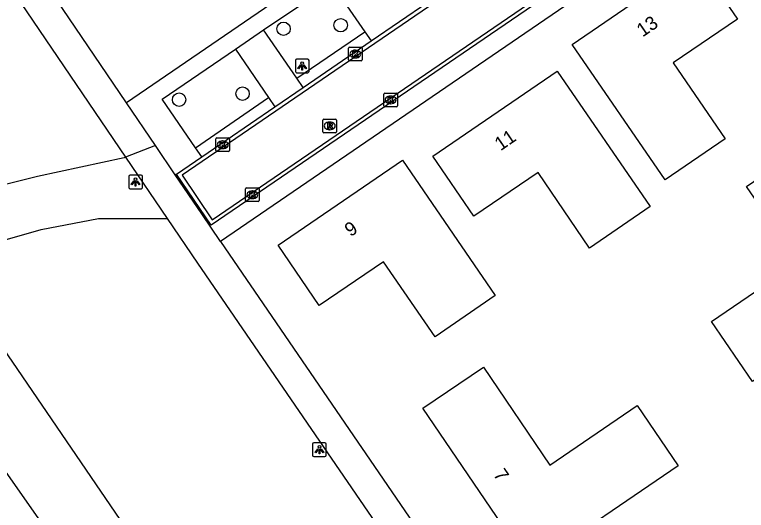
# Model space of a CAD drawing. Extents: x 155275 to 156263, y 382654 to 383635.
# Drawn here: x 155466.7 to 155520.2, y 383140.8 to 383177 of the extents above; entities that cross this region are included whole.
import ezdxf

# ---------------------------------------------------------------- set-up
doc = ezdxf.new("R2010")
doc.units = 0
for name, color, linetype in [('IMGEO_Boom', 7, 'Continuous'), ('IMGEO_Groenvoorziening', 7, 'Continuous'), ('IMGEO_Kolk', 7, 'Continuous'), ('IMGEO_Lichtpunt', 7, 'Continuous'), ('IMGEO_Pand', 7, 'Continuous'), ('IMGEO_Pand_nummerreeks', 7, 'Continuous'), ('IMGEO_Parkeervlak_open', 7, 'Continuous'), ('IMGEO_Rijbaan_lokaal_gesloten', 7, 'Continuous'), ('IMGEO_Rioolput', 7, 'Continuous'), ('IMGEO_Voetpad_halfverhard', 7, 'Continuous'), ('IMGEO_Voetpad_open', 7, 'Continuous')]:
    doc.layers.add(name, color=color, linetype=linetype)

msp = doc.modelspace()

# ---------------------------------------------------------------- linework, layer by layer
at = {"layer": 'IMGEO_Boom'}
for centre in [(155490.508, 383176.25), (155486.336, 383175.992), (155478.702, 383170.812), (155483.34, 383171.251)]:
    msp.add_circle(centre, 0.489, dxfattribs=at)
at = {"layer": 'IMGEO_Groenvoorziening'}
msp.add_lwpolyline([(155532.26, 383055.303), (155462.233, 383157.915)], dxfattribs=at)
at = {"layer": 'IMGEO_Kolk'}
for p, q in [((155491.078, 383173.722), (155491.078, 383174.574)), ((155491.153, 383174.648), (155492.005, 383174.648)), ((155492.079, 383174.574), (155492.079, 383173.722)), ((155491.566, 383174.428), (155491.591, 383174.428)), ((155492.005, 383173.648), (155491.153, 383173.648)), ((155491.589, 383173.868), (155491.564, 383173.868)), ((155493.729, 383171.297), (155494.581, 383171.297)), ((155493.654, 383170.371), (155493.654, 383171.223)), ((155494.142, 383171.077), (155494.167, 383171.077)), ((155494.655, 383171.223), (155494.655, 383170.371)), ((155494.581, 383170.297), (155493.729, 383170.297)), ((155494.165, 383170.517), (155494.14, 383170.517)), ((155481.39, 383167.092), (155481.39, 383167.944)), ((155481.465, 383168.018), (155482.317, 383168.018)), ((155481.878, 383167.798), (155481.903, 383167.798)), ((155482.391, 383167.944), (155482.391, 383167.092)), ((155482.317, 383167.018), (155481.465, 383167.018)), ((155481.901, 383167.238), (155481.876, 383167.238)), ((155483.626, 383164.367), (155484.478, 383164.367)), ((155483.551, 383163.441), (155483.551, 383164.293)), ((155484.039, 383164.147), (155484.064, 383164.147)), ((155484.552, 383164.293), (155484.552, 383163.441)), ((155484.478, 383163.367), (155483.626, 383163.367)), ((155484.062, 383163.587), (155484.037, 383163.587))]:
    msp.add_line(p, q, dxfattribs=at)
for points in [[(155491.078, 383173.722), (155491.078, 383174.574)], [(155491.153, 383174.648), (155492.005, 383174.648)], [(155492.079, 383174.574), (155492.079, 383173.722)], [(155491.399, 383174.348), (155491.522, 383174.348), (155491.522, 383174.197), (155491.652, 383174.348), (155491.816, 383174.348), (155491.67, 383174.197), (155491.823, 383173.948), (155491.671, 383173.948), (155491.586, 383174.112), (155491.522, 383174.045), (155491.522, 383173.948), (155491.399, 383173.948), (155491.399, 383174.348)], [(155492.005, 383173.648), (155491.153, 383173.648)], [(155493.729, 383171.297), (155494.581, 383171.297)], [(155493.654, 383170.371), (155493.654, 383171.223)], [(155493.975, 383170.997), (155494.098, 383170.997), (155494.098, 383170.846), (155494.228, 383170.997), (155494.392, 383170.997), (155494.246, 383170.846), (155494.399, 383170.597), (155494.247, 383170.597), (155494.162, 383170.761), (155494.098, 383170.694), (155494.098, 383170.597), (155493.975, 383170.597), (155493.975, 383170.997)], [(155494.655, 383171.223), (155494.655, 383170.371)], [(155494.581, 383170.297), (155493.729, 383170.297)], [(155481.39, 383167.092), (155481.39, 383167.944)], [(155481.465, 383168.018), (155482.317, 383168.018)], [(155481.711, 383167.718), (155481.834, 383167.718), (155481.834, 383167.567), (155481.964, 383167.718), (155482.128, 383167.718), (155481.982, 383167.567), (155482.135, 383167.318), (155481.983, 383167.318), (155481.898, 383167.482), (155481.834, 383167.415), (155481.834, 383167.318), (155481.711, 383167.318), (155481.711, 383167.718)], [(155482.391, 383167.944), (155482.391, 383167.092)], [(155482.317, 383167.018), (155481.465, 383167.018)], [(155483.626, 383164.367), (155484.478, 383164.367)], [(155483.551, 383163.441), (155483.551, 383164.293)], [(155483.872, 383164.067), (155483.995, 383164.067), (155483.995, 383163.916), (155484.125, 383164.067), (155484.289, 383164.067), (155484.143, 383163.916), (155484.296, 383163.667), (155484.144, 383163.667), (155484.059, 383163.831), (155483.995, 383163.764), (155483.995, 383163.667), (155483.872, 383163.667), (155483.872, 383164.067)], [(155484.552, 383164.293), (155484.552, 383163.441)], [(155484.478, 383163.367), (155483.626, 383163.367)]]:
    msp.add_lwpolyline(points, dxfattribs=at)
for centre, start, end in [((155491.155, 383174.572), 91.552, 178.448), ((155491.155, 383174.572), 91.552, 178.448), ((155492.003, 383174.572), 1.552, 88.448), ((155492.003, 383174.572), 1.552, 88.448), ((155491.155, 383173.724), 181.552, 268.448), ((155491.155, 383173.724), 181.552, 268.448), ((155492.003, 383173.724), 271.552, 358.448), ((155492.003, 383173.724), 271.552, 358.448), ((155493.731, 383171.221), 91.552, 178.448), ((155493.731, 383171.221), 91.552, 178.448), ((155494.579, 383171.221), 1.552, 88.448), ((155494.579, 383171.221), 1.552, 88.448), ((155493.731, 383170.373), 181.552, 268.448), ((155493.731, 383170.373), 181.552, 268.448), ((155494.579, 383170.373), 271.552, 358.448), ((155494.579, 383170.373), 271.552, 358.448), ((155481.467, 383167.942), 91.552, 178.448), ((155481.467, 383167.942), 91.552, 178.448), ((155482.315, 383167.942), 1.552, 88.448), ((155482.315, 383167.942), 1.552, 88.448), ((155481.467, 383167.094), 181.552, 268.448), ((155481.467, 383167.094), 181.552, 268.448), ((155482.315, 383167.094), 271.552, 358.448), ((155482.315, 383167.094), 271.552, 358.448), ((155483.628, 383164.291), 91.552, 178.448), ((155483.628, 383164.291), 91.552, 178.448), ((155484.476, 383164.291), 1.552, 88.448), ((155484.476, 383164.291), 1.552, 88.448), ((155483.628, 383163.443), 181.552, 268.448), ((155483.628, 383163.443), 181.552, 268.448), ((155484.476, 383163.443), 271.552, 358.448), ((155484.476, 383163.443), 271.552, 358.448)]:
    msp.add_arc(centre, 0.0765, start, end, dxfattribs=at)
for centre, major_axis, ratio, start_param, end_param in [((155491.565, 383174.148), (-0.387, 0.002), 0.722429, 4.712389, 7.853982), ((155491.59, 383174.148), (-0.39, 0.002), 0.717154, 1.570796, 4.712389), ((155494.141, 383170.797), (-0.387, 0.002), 0.722429, 4.712389, 7.853982), ((155494.166, 383170.797), (-0.39, 0.002), 0.717154, 1.570796, 4.712389), ((155481.877, 383167.518), (-0.387, 0.002), 0.722429, 4.712389, 7.853982), ((155481.902, 383167.518), (-0.39, 0.002), 0.717154, 1.570796, 4.712389), ((155484.038, 383163.867), (-0.387, 0.002), 0.722429, 4.712389, 7.853982), ((155484.063, 383163.867), (-0.39, 0.002), 0.717154, 1.570796, 4.712389)]:
    msp.add_ellipse(centre, major_axis=major_axis, ratio=ratio, start_param=start_param, end_param=end_param, dxfattribs=at)
at = {"layer": 'IMGEO_Lichtpunt'}
for p, q in [((155487.198, 383173.685), (155487.198, 383172.878)), ((155487.198, 383173.685), (155487.198, 383172.878)), ((155488.1, 383173.78), (155487.292, 383173.78)), ((155488.1, 383173.78), (155487.292, 383173.78)), ((155488.194, 383172.878), (155488.194, 383173.685)), ((155488.194, 383172.878), (155488.194, 383173.685)), ((155487.292, 383172.784), (155488.1, 383172.784)), ((155487.292, 383172.784), (155488.1, 383172.784)), ((155475.023, 383165.21), (155475.023, 383164.403)), ((155475.023, 383165.21), (155475.023, 383164.403)), ((155475.925, 383165.305), (155475.117, 383165.305)), ((155475.925, 383165.305), (155475.117, 383165.305)), ((155476.019, 383164.403), (155476.019, 383165.21)), ((155476.019, 383164.403), (155476.019, 383165.21)), ((155475.117, 383164.309), (155475.925, 383164.309)), ((155475.117, 383164.309), (155475.925, 383164.309)), ((155488.456, 383145.64), (155488.456, 383144.833)), ((155488.456, 383145.64), (155488.456, 383144.833)), ((155489.358, 383145.735), (155488.55, 383145.735)), ((155489.358, 383145.735), (155488.55, 383145.735)), ((155489.452, 383144.833), (155489.452, 383145.64)), ((155489.452, 383144.833), (155489.452, 383145.64)), ((155488.55, 383144.739), (155489.358, 383144.739)), ((155488.55, 383144.739), (155489.358, 383144.739))]:
    msp.add_line(p, q, dxfattribs=at)
for points in [[(155487.572, 383173.349), (155487.611, 383173.321), (155487.423, 383173.059), (155487.385, 383173.086), (155487.572, 383173.349)], [(155487.674, 383173.301), (155487.721, 383173.301), (155487.721, 383172.979), (155487.674, 383172.979), (155487.674, 383173.301)], [(155487.784, 383173.321), (155487.822, 383173.348), (155488.009, 383173.086), (155487.97, 383173.058), (155487.784, 383173.321)], [(155475.397, 383164.874), (155475.436, 383164.846), (155475.248, 383164.584), (155475.21, 383164.611), (155475.397, 383164.874)], [(155475.609, 383164.846), (155475.647, 383164.873), (155475.834, 383164.611), (155475.795, 383164.583), (155475.609, 383164.846)], [(155475.499, 383164.826), (155475.546, 383164.826), (155475.546, 383164.504), (155475.499, 383164.504), (155475.499, 383164.826)], [(155488.83, 383145.304), (155488.869, 383145.276), (155488.681, 383145.014), (155488.643, 383145.041), (155488.83, 383145.304)], [(155488.932, 383145.256), (155488.979, 383145.256), (155488.979, 383144.934), (155488.932, 383144.934), (155488.932, 383145.256)], [(155489.042, 383145.276), (155489.08, 383145.303), (155489.267, 383145.041), (155489.228, 383145.013), (155489.042, 383145.276)]]:
    msp.add_lwpolyline(points, dxfattribs=at)
for centre in [(155487.697, 383173.483), (155475.522, 383165.008), (155488.955, 383145.438)]:
    msp.add_circle(centre, 0.0994, dxfattribs=at)
for centre, start, end in [((155487.292, 383173.685), 90, 180), ((155487.292, 383173.685), 90, 180), ((155488.1, 383173.685), 0, 90), ((155488.1, 383173.685), 0, 90), ((155487.292, 383172.878), 180, 270), ((155487.292, 383172.878), 180, 270), ((155488.1, 383172.878), 270, 0), ((155488.1, 383172.878), 270, 360), ((155475.117, 383165.21), 90, 180), ((155475.117, 383165.21), 90, 180), ((155475.925, 383165.21), 0, 90), ((155475.925, 383165.21), 0, 90), ((155475.117, 383164.403), 180, 270), ((155475.117, 383164.403), 180, 270), ((155475.925, 383164.403), 270, 0), ((155475.925, 383164.403), 270, 360), ((155488.55, 383145.64), 90, 180), ((155488.55, 383145.64), 90, 180), ((155489.358, 383145.64), 0, 90), ((155489.358, 383145.64), 0, 90), ((155488.55, 383144.833), 180, 270), ((155488.55, 383144.833), 180, 270), ((155489.358, 383144.833), 270, 0), ((155489.358, 383144.833), 270, 360)]:
    msp.add_arc(centre, 0.0946, start, end, dxfattribs=at)
at = {"layer": 'IMGEO_Pand'}
for points in [[(155518.605, 383167.962), (155514.21, 383164.968), (155507.415, 383174.849), (155516.52, 383181.09), (155519.515, 383176.693), (155514.811, 383173.493), (155518.605, 383167.962)], [(155513.126, 383163.01), (155508.698, 383159.972), (155504.944, 383165.502), (155500.249, 383162.295), (155497.248, 383166.689), (155506.329, 383172.897), (155513.126, 383163.01)], [(155531.374, 383157.564), (155520.608, 383150.215), (155517.615, 383154.608), (155523.957, 383158.929), (155520.168, 383164.469), (155524.592, 383167.478), (155531.374, 383157.564)], [(155501.806, 383156.503), (155497.424, 383153.478), (155493.637, 383158.963), (155488.93, 383155.776), (155485.946, 383160.182), (155495.036, 383166.388), (155501.806, 383156.503)], [(155500.946, 383151.275), (155505.801, 383144.112), (155512.165, 383148.464), (155515.17, 383144.069), (155504.385, 383136.699), (155496.513, 383148.271), (155500.946, 383151.275)]]:
    msp.add_lwpolyline(points, dxfattribs=at)
at = {"layer": 'IMGEO_Parkeervlak_open'}
for points in [[(155489.868, 383179.279), (155492.272, 383175.772)], [(155487.309, 383172.386), (155484.874, 383175.918)], [(155482.819, 383174.511), (155485.236, 383170.964)]]:
    msp.add_lwpolyline(points, dxfattribs=at)
at = {"layer": 'IMGEO_Rijbaan_lokaal_gesloten'}
for points in [[(155619.924, 383262.117), (155620.091, 383261.877), (155574.69, 383230.764), (155525.625, 383197.223), (155478.919, 383165.304), (155481.12, 383162.042), (155527.802, 383193.934), (155576.261, 383227.078), (155622.367, 383258.594), (155622.544, 383258.352)], [(155517.341, 383186.428), (155481.036, 383161.64), (155478.515, 383165.379)], [(155492.732, 383175.102), (155496.888, 383177.944)], [(155487.774, 383171.711), (155492.732, 383175.102)], [(155485.695, 383170.29), (155487.774, 383171.711)], [(155480.355, 383166.638), (155485.695, 383170.29)], [(155478.515, 383165.379), (155480.355, 383166.638)]]:
    msp.add_lwpolyline(points, dxfattribs=at)
at = {"layer": 'IMGEO_Rioolput'}
for p, q in [((155489.21, 383168.47), (155489.21, 383169.322)), ((155489.285, 383169.396), (155490.137, 383169.396)), ((155489.698, 383169.176), (155489.723, 383169.176)), ((155490.211, 383169.322), (155490.211, 383168.47)), ((155489.721, 383168.616), (155489.696, 383168.616)), ((155490.137, 383168.396), (155489.285, 383168.396))]:
    msp.add_line(p, q, dxfattribs=at)
for points in [[(155489.21, 383168.47), (155489.21, 383169.322)], [(155489.285, 383169.396), (155490.137, 383169.396)], [(155490.211, 383169.322), (155490.211, 383168.47)], [(155489.799, 383169.094), (155489.547, 383169.096), (155489.547, 383168.696)], [(155489.547, 383168.696), (155489.671, 383168.696), (155489.671, 383168.858), (155489.682, 383168.858)], [(155489.725, 383169.015), (155489.671, 383169.015), (155489.671, 383168.934)], [(155489.671, 383168.934), (155489.723, 383168.934)], [(155489.729, 383168.829), (155489.8, 383168.696), (155489.94, 383168.696), (155489.875, 383168.822)], [(155490.137, 383168.396), (155489.285, 383168.396)]]:
    msp.add_lwpolyline(points, dxfattribs=at)
for centre, radius, start, end in [((155489.287, 383169.32), 0.0765, 91.552, 178.448), ((155489.287, 383169.32), 0.0765, 91.552, 178.448), ((155490.135, 383169.32), 0.0765, 1.552, 88.448), ((155490.135, 383169.32), 0.0765, 1.552, 88.448), ((155489.681, 383168.805), 0.0533, 26.0293, 88.6989), ((155489.707, 383169.123), 0.19, 274.7715, 282.9687), ((155489.731, 383168.919), 0.0964, 77.0061, 93.1865), ((155489.745, 383168.976), 0.0378, 276.6634, 79.6772), ((155489.798, 383168.984), 0.109, 350.3612, 89.416), ((155489.796, 383168.984), 0.112, 277.5842, 350.9817), ((155489.78, 383168.769), 0.108, 29.5134, 73.7905), ((155489.287, 383168.472), 0.0765, 181.552, 268.448), ((155489.287, 383168.472), 0.0765, 181.552, 268.448), ((155490.135, 383168.472), 0.0765, 271.552, 358.448), ((155490.135, 383168.472), 0.0765, 271.552, 358.448)]:
    msp.add_arc(centre, radius, start, end, dxfattribs=at)
for centre, major_axis, ratio, start_param, end_param in [((155489.697, 383168.896), (-0.387, 0.002), 0.722429, 4.712389, 7.853982), ((155489.722, 383168.896), (-0.39, 0.002), 0.717154, 1.570796, 4.712389)]:
    msp.add_ellipse(centre, major_axis=major_axis, ratio=ratio, start_param=start_param, end_param=end_param, dxfattribs=at)
at = {"layer": 'IMGEO_Voetpad_halfverhard'}
for points in [[(155474.787, 383166.602), (155474.676, 383166.559), (155468.343, 383165.205), (155465.923, 383164.58), (155464.413, 383163.773), (155463.012, 383162.789), (155461.359, 383162.343), (155459.782, 383162.343)], [(155462.233, 383157.915), (155463.849, 383159.263), (155465.995, 383160.571), (155468.617, 383161.331), (155472.813, 383162.127), (155477.826, 383162.127)], [(155462.233, 383157.915), (155462.079, 383157.786), (155460.804, 383156.197), (155460.205, 383154.218), (155460.309, 383152.942), (155463.293, 383147.493), (155476.061, 383129.31), (155480.081, 383123.249), (155485.32, 383114.545), (155492.386, 383101.857), (155501.64, 383091.213)]]:
    msp.add_lwpolyline(points, dxfattribs=at)
at = {"layer": 'IMGEO_Voetpad_open'}
for points in [[(155423.012, 383241.856), (155425.856, 383237.778), (155442.284, 383214.464), (155442.318, 383214.415), (155474.787, 383166.602)], [(155474.854, 383170.583), (155445.521, 383213.792), (155444.194, 383215.772), (155444.08, 383215.943), (155433.772, 383231.088), (155428.923, 383238.236)], [(155512.727, 383196.487), (155474.854, 383170.583)], [(155518.055, 383185.291), (155481.726, 383160.46)], [(155484.874, 383175.918), (155489.868, 383179.279)], [(155482.819, 383174.511), (155484.874, 383175.918)], [(155487.309, 383172.386), (155492.272, 383175.772)], [(155492.272, 383175.772), (155492.732, 383175.102)], [(155479.896, 383167.306), (155477.463, 383170.842), (155482.819, 383174.511)], [(155487.774, 383171.711), (155487.309, 383172.386)], [(155479.896, 383167.306), (155485.236, 383170.964)], [(155485.236, 383170.964), (155485.695, 383170.29)], [(155476.977, 383167.454), (155474.854, 383170.583)], [(155476.977, 383167.454), (155474.787, 383166.602)], [(155478.425, 383165.321), (155476.977, 383167.454)], [(155480.355, 383166.638), (155479.896, 383167.306)], [(155474.787, 383166.602), (155477.826, 383162.127)], [(155478.515, 383165.379), (155478.425, 383165.321)], [(155481.726, 383160.46), (155480.355, 383162.479), (155478.425, 383165.321)], [(155477.826, 383162.127), (155480.034, 383158.875), (155521.541, 383098.327), (155531.269, 383084.388), (155531.326, 383084.304)], [(155481.726, 383160.46), (155502.376, 383130.281), (155519.947, 383104.719), (155533.096, 383085.724), (155535.7, 383087.843), (155548.446, 383098.264), (155549.474, 383096.699)]]:
    msp.add_lwpolyline(points, dxfattribs=at)

# ---------------------------------------------------------------- texts
at = {"layer": 'IMGEO_Pand_nummerreeks'}
for s, rotation, p in [('13', 34.429, (155512.574, 383175.354)), ('11', 34.3603, (155502.193, 383167.041)), ('9', 34.3202, (155491.231, 383160.763)), ('7', 304.2283, (155501.626, 383143.421))]:
    msp.add_text(s, height=1, rotation=rotation, dxfattribs=at).set_placement(p)

doc.saveas('drawing.dxf')
